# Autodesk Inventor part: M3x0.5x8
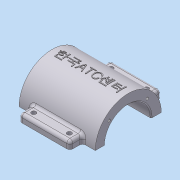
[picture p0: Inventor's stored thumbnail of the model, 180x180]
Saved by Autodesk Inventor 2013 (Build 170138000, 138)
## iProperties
Company: 한국ATC센터
Created: 2009-02
Part Number: M3x0.5x8
Document SubType Name: Modeling
Designer: KYOUNG IL JANG
Density: 2.71 g/cm^3
Mass: 199.244 g
Surface Area: 195.422 cm^2
Volume: 73.522 cm^3
Material: 알루미늄-6061
Vendor: CBT Solutions
Author: KYOUNG IL JANG
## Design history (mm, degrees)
sketch "스케치1"
  geometry: L1 (-45, 40)-(45, 40); L2 (45, 40)-(45, -40); L3 (45, -40)-(-45, -40); L4 (-45, -40)-(-45, 40); 3 further points
  constraints: 8 end point, 2 midpoint, 2 parallel, 1 horizontal, 1 horizontal alignment, 1 perpendicular, 1 vertical alignment
  dimensions: "d0" = 90 distance of L2.end L3.end; "d1" = 80 distance of L1.end L2.end
extrude "돌출1" new body sketch "스케치1" distance "d2" = 10; taper "d3" = 0 deg
sketch "스케치2"
  geometry: L1 (40, 0)-(-40, 0) reference; C1 r 32.5 at (0, 80); 2 further points
  constraints: 1 centre point, 1 midpoint, 1 vertical alignment
  dimensions: "d4" = 65 diameter of C1; "d5" = 80 distance from line of C1.centre L1
extrude "돌출2" join sketch "스케치2" stored distance "d6" = 75; taper "d7" = 0 deg
sketch "스케치3"
  geometry: L1 (-7.5, -20)-(7.5, -20); L2 (7.5, 20)-(-7.5, 20); A1 r 20 centre (7.5, 0) between (7.5, -20) and (7.5, 20); A2 r 20 centre (-7.5, 0) between (-7.5, 20) and (-7.5, -20); 2 further points
  constraints: 4 end point, 4 point on circle, 4 tangent, 2 centre point, 1 horizontal, 1 horizontal alignment, 1 midpoint, 1 parallel, 1 vertical alignment
  dimensions: "d8" = 20 radius of A2; "d9" = 55 dimension on A1 A2
extrude "돌출3" join sketch "스케치3" stored distance "d10" = 75; taper "d11" = 0 deg
fillet "모깎기1" dims "d12" = 10
sketch "스케치4"
  geometry: L1 (-45, 0)-(-45, 10) reference; L2 (37.5, 47.5)-(-37.5, 47.5) reference; L3 (-45, 10)-(-27.513, 47.5); 1 further point
  constraints: 2 end point, 1 point on line
  dimensions: "d13" = 25 deg angle of L3 L1
sketch "스케치5"
  geometry: L1 (-40, 0)-(-40, 10) reference; L2 (-40, 10)-(-22.912, 56.95); 2 further points
  constraints: 2 end point, 2 other
  dimensions: "d14" = 20 deg angle of L2 L1
feature "리브1" dims "d15" = 1, "d16" = 6, "d17" = 0
feature "리브2" dims "d18" = 1, "d19" = 6, "d20" = 0
fillet "모깎기2" dims "d21" = 3
fillet "모깎기3" dims "d22" = 3
fillet "모깎기4" dims "d23" = 3
fillet "모깎기5" dims "d24" = 3
fillet "모깎기6" dims "d25" = 3
fillet "모깎기7" dims "d26" = 3
fillet "모깎기8" dims "d27" = 3
sketch "스케치6"
  geometry: A1 r 10 centre (35, -30) between (35, -40) and (45, -30) reference; 1 further point
hole "구멍1" sketch "스케치6" at (35, -30) diameter "d28" = 10; stored, may be unused: countersink angle "d32" = 90 deg, drill point angle "d34" = 118 deg; dims "d29" = 6, "d30" = 4, "d31" = 2, "d33" = 8
hole "구멍2" diameter "d37" = 45; stored, may be unused: countersink angle "d41" = 90 deg, drill point angle "d43" = 118 deg; dims "d35" = 10, "d36" = 10, "d38" = 6, "d39" = 4, "d40" = 2, "d42" = 8
sketch "스케치7"
  geometry: C1 r 22.5 at (0, 0) reference; 2 further points
  dimensions: "d44" = 135 deg dimension on C1.centre point (-18.738, 18.738) point (80, 0); "d45" = 26.5 distance of point (-18.738, 18.738) C1.centre
hole "구멍3" sketch "스케치7" at (-18.738, 18.738) diameter "d46" = 2.459; stored, may be unused: countersink angle "d50" = 90 deg, drill point angle "d52" = 118 deg; dims "d47" = 8, "d48" = 4, "d49" = 2, "d51" = 10
node "작업 평면1"
chamfer "모따기1" distance "d69" = 1; stored, may be unused: second distance "d70" = 2, angle "d71" = 45 deg
sketch "스케치9"
  geometry: L1 (-31.623, 87.5)-(-45, 87.5); L2 (-45, 87.5)-(-45, 72.5); L3 (-45, 72.5)-(-31.623, 72.5); A1 r 32.5 centre (0, 80) between (-31.623, 87.5) and (-31.623, 72.5) reference; 1 further point
  constraints: 6 end point, 2 parallel, 2 point on circle, 1 horizontal, 1 perpendicular
  dimensions: "d73" = 15 distance of L1.end L2.end; "d74" = 45 distance from line of A1.centre L2
extrude "돌출5" join sketch "스케치9" stored distance "d75" = 50; taper "d76" = 0 deg
fillet "모깎기10" dims "d77" = 3
fillet "모깎기11" dims "d78" = 3
sketch "스케치10"
  geometry: L1 (100.378, 66.389)-(0, 66.389); L2 (0, 66.389)-(0, -76.978); L3 (0, -76.978)-(100.378, -76.978); L4 (100.378, -76.978)-(100.378, 66.389); C1 r 32.5 at (0, 0) reference; 1 further point
  constraints: 8 end point, 2 parallel, 1 horizontal, 1 perpendicular, 1 point on line
extrude "돌출6" cut sketch "스케치10" stored distance "d79" = 10; taper "d80" = 0 deg
sketch "스케치11"
  geometry: C1 r 1.621 at (4.5, 4) reference; C2 r 1.621 at (39.5, 4) reference; 1 further point
hole "구멍5" sketch "스케치11" at (39.5, 4), (4.5, 4) diameter "d81" = 4.5; stored, may be unused: countersink angle "d85" = 90 deg, drill point angle "d87" = 118 deg; dims "d82" = 6, "d83" = 4, "d84" = 2, "d86" = 8
node "작업 평면2"
sketch "스케치12"
  geometry: 2 further points
  constraints: 1 coincident, 1 other
feature "엠보싱1" sketch "스케치12" dims "d8" = 20, "d9" = 55, "d88" = 0.5, "d89" = 0
node "솔리드1"
mirror "대칭1"
mirror "대칭2"
mirror "대칭3"
mirror "대칭4"
pattern_circular "원형 패턴1" dims angle "d54" = 360 deg
mirror "대칭5"
mirror "대칭6"
mirror "대칭7"
node "참조1"
node "참조2"
other parameters: "d56" = -117
